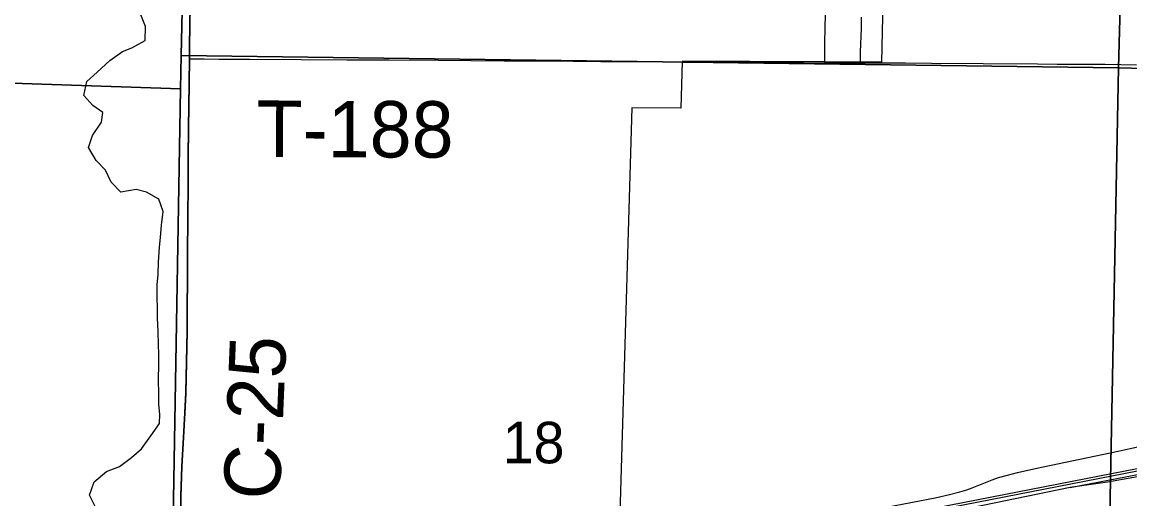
# Model space of a CAD drawing. Extents: x 0 to 34, y 0 to 22.
# Drawn here: x 5.615 to 6.731, y 18.139 to 18.619 of the extents above; entities that cross this region are included whole.
import ezdxf

# ---------------------------------------------------------------- set-up
doc = ezdxf.new("R2010")
doc.units = 0
for name, color, linetype in [('GM_X_City_Street', 7, 'Continuous'), ('GM_X_Corporation', 7, 'Continuous'), ('GM_X_County_Road', 7, 'Continuous'), ('GM_X_County_Road_Text', 7, 'Continuous'), ('GM_X_Minor_River', 7, 'Continuous'), ('GM_X_Rail_Line', 7, 'Continuous'), ('GM_X_Section_Text', 7, 'Continuous'), ('GM_X_Township_Road', 7, 'Continuous'), ('GM_X_Township_Road_Text', 7, 'Continuous')]:
    doc.layers.add(name, color=color, linetype=linetype)

msp = doc.modelspace()

# ---------------------------------------------------------------- linework, layer by layer
at = {"layer": 'GM_X_City_Street'}
msp.add_lwpolyline([(6.7198, 18.1874), (6.7348, 18.1907), (6.7634, 18.1967), (6.7983, 18.2033), (6.8423, 18.2119), (6.8863, 18.2201), (6.9106, 18.2247), (6.9292, 18.2281), (6.9377, 18.2295)], dxfattribs=at)
at = {"layer": 'GM_X_Corporation'}
for points in [[(6.7472, 19.5762), (6.72, 18.5734), (5.7756, 18.586), (5.7974, 19.5584), (5.7981, 19.5979)], [(4.8036, 19.5906), (5.7974, 19.5584), (5.7756, 18.586), (5.7749, 18.5522), (4.7775, 18.5857)], [(6.7486, 19.5865), (7.7504, 19.5655), (7.7346, 18.5471), (6.72, 18.5734), (6.7472, 19.5762)], [(4.7775, 18.5857), (5.7749, 18.5522), (5.7585, 17.5867), (5.7581, 17.5537), (4.7439, 17.5807)], [(5.7756, 18.586), (6.72, 18.5734), (6.7004, 17.5689), (5.7585, 17.5867), (5.7749, 18.5522)], [(6.72, 18.5734), (7.7346, 18.5471), (7.7016, 17.5373), (6.7004, 17.5689)]]:
    msp.add_lwpolyline(points, close=True, dxfattribs=at)
for points in [[(6.4924, 19.0846), (6.4812, 18.579), (6.4596, 18.5792), (6.4241, 18.5793), (6.3486, 18.5797), (6.2805, 18.5799), (6.2791, 18.5328), (6.2298, 18.5331), (6.2163, 18.0789)], [(5.7754, 18.121), (5.7754, 18.1421), (5.7765, 18.1719), (5.7779, 18.2011), (5.7795, 18.2259), (5.7805, 18.2463), (5.7818, 18.3085), (5.7822, 18.3843), (5.7823, 18.4241), (5.7826, 18.4557), (5.7829, 18.4831), (5.7832, 18.5129), (5.7839, 18.5576), (5.7841, 18.5832), (5.7841, 18.5931), (5.7845, 18.6185), (5.7851, 18.6508)], [(5.7851, 18.6508), (5.7845, 18.6185), (5.7841, 18.5931), (5.7841, 18.5832), (5.7839, 18.5576), (5.7832, 18.5129), (5.7829, 18.4831), (5.7826, 18.4557), (5.7823, 18.4241), (5.7822, 18.3843), (5.7818, 18.3085), (5.7805, 18.2463), (5.7795, 18.2259), (5.7779, 18.2011), (5.7765, 18.1719), (5.7754, 18.1421), (5.7754, 18.121)]]:
    msp.add_lwpolyline(points, dxfattribs=at)
at = {"layer": 'GM_X_County_Road'}
for points in [[(5.7843, 18.5826), (5.7844, 18.5925), (5.7847, 18.618), (5.7853, 18.6503), (5.7861, 18.6776), (5.7865, 18.6981), (5.787, 18.7354), (5.7874, 18.7485)], [(5.7774, 18.1855), (5.7781, 18.2005), (5.7797, 18.2253), (5.7807, 18.2458), (5.782, 18.3079), (5.7824, 18.3837), (5.7825, 18.4235), (5.7828, 18.4552), (5.7831, 18.4825), (5.7834, 18.5123), (5.7841, 18.5571), (5.7843, 18.5826)], [(5.7764, 18.0824), (5.7756, 18.1204), (5.7757, 18.1416), (5.7767, 18.1714), (5.7774, 18.1855)], [(6.2164, 18.0781), (6.2364, 18.0818), (6.2731, 18.0887), (6.3042, 18.0949), (6.348, 18.1038), (6.3925, 18.1126), (6.4413, 18.122), (6.4864, 18.131), (6.5352, 18.1404), (6.5498, 18.1436), (6.5601, 18.1462), (6.5673, 18.1484), (6.5726, 18.1502), (6.5842, 18.1549), (6.5928, 18.1583), (6.5992, 18.1606), (6.6081, 18.1632), (6.6183, 18.1658), (6.6377, 18.17), (6.6809, 18.1792), (6.7198, 18.1874)]]:
    msp.add_lwpolyline(points, dxfattribs=at)
at = {"layer": 'GM_X_Minor_River'}
msp.add_lwpolyline([(5.6906, 18.1282), (5.6832, 18.1428), (5.6881, 18.1563), (5.7004, 18.1667), (5.7134, 18.1718), (5.7257, 18.181), (5.7357, 18.1896), (5.7451, 18.2027), (5.754, 18.215), (5.7542, 18.2245), (5.7533, 18.2344), (5.7531, 18.2439), (5.753, 18.2602), (5.7533, 18.2738), (5.7531, 18.2845), (5.7529, 18.2947), (5.7524, 18.3073), (5.7519, 18.3217), (5.7517, 18.3316), (5.7516, 18.3418), (5.7514, 18.3547), (5.7524, 18.3653), (5.753, 18.3775), (5.7537, 18.3926), (5.755, 18.4025), (5.756, 18.415), (5.7574, 18.4286), (5.7531, 18.4412), (5.7407, 18.4483), (5.7305, 18.4508), (5.7149, 18.448), (5.7053, 18.4581), (5.6994, 18.4704), (5.6901, 18.48), (5.6824, 18.4931), (5.6864, 18.5051), (5.6954, 18.5186), (5.6968, 18.5285), (5.6867, 18.5355), (5.6777, 18.5455), (5.6807, 18.5595), (5.6911, 18.5692), (5.7038, 18.5807), (5.7165, 18.59), (5.7261, 18.5936), (5.7395, 18.6009), (5.7398, 18.6149), (5.7336, 18.6302)], dxfattribs=at)
at = {"layer": 'GM_X_Rail_Line'}
msp.add_line((6.6714, 18.1505), (8.0077, 18.4121), dxfattribs=at)
for points in [[(2.1, 17.2578), (2.1839, 17.2743), (2.7373, 17.3807), (3.3215, 17.4979), (3.9612, 17.6228), (4.5554, 17.74), (5.1565, 17.8564), (5.7754, 17.979), (6.3342, 18.0908), (6.9022, 18.2018), (7.3492, 18.2882), (7.4239, 18.3027), (8.0092, 18.4168), (8.4623, 18.5082), (8.9, 18.5958)], [(2.1, 17.2555), (2.1844, 17.272), (2.7377, 17.3784), (3.3219, 17.4956), (3.9616, 17.6205), (4.5558, 17.7377), (5.157, 17.8541), (5.7759, 17.9767), (6.3346, 18.0885), (6.9026, 18.1995), (7.3496, 18.2859), (7.4243, 18.3004), (8.0097, 18.4146), (8.4624, 18.5056), (8.9, 18.5934)], [(6.7516, 18.164), (6.7353, 18.1608), (6.709, 18.1559), (6.6714, 18.1505)], [(6.6714, 18.1505), (6.5393, 18.1236), (6.3844, 18.0928), (6.2895, 18.0748), (6.2521, 18.072)]]:
    msp.add_lwpolyline(points, dxfattribs=at)
at = {"layer": 'GM_X_Township_Road'}
for points in [[(6.4242, 18.5786), (6.4242, 18.5993), (6.4248, 18.6272)], [(6.4608, 18.6243), (6.4607, 18.613), (6.4599, 18.5895), (6.4599, 18.5857), (6.4597, 18.5785)], [(5.7843, 18.5826), (5.7886, 18.5826), (5.799, 18.5825), (5.814, 18.5822), (5.8307, 18.5822), (5.845, 18.5822), (5.8966, 18.5819), (5.9425, 18.5816), (5.9649, 18.5815), (5.9854, 18.5814), (6.0345, 18.581), (6.101, 18.5805), (6.1234, 18.5804), (6.1707, 18.58), (6.1986, 18.5797), (6.2353, 18.5797), (6.2689, 18.5794), (6.2806, 18.5792)], [(6.2806, 18.5792), (6.3183, 18.5792), (6.3487, 18.579), (6.3866, 18.5788), (6.4027, 18.5788), (6.4242, 18.5786)], [(6.4242, 18.5786), (6.4382, 18.5784), (6.4597, 18.5785), (6.4617, 18.5785), (6.4813, 18.5783)], [(6.4813, 18.5783), (6.5054, 18.5783), (6.5315, 18.5781), (6.5837, 18.5777), (6.6384, 18.5775), (6.6582, 18.5772), (6.7067, 18.577), (6.738, 18.5764)]]:
    msp.add_lwpolyline(points, dxfattribs=at)

# ---------------------------------------------------------------- texts
at = {"layer": 'GM_X_County_Road_Text'}
msp.add_text('C-25', height=0.05682, rotation=87.6286, dxfattribs=at).set_placement((5.8749, 18.1376))
at = {"layer": 'GM_X_Section_Text'}
msp.add_text('18', height=0.04186, rotation=0, dxfattribs=at).set_placement((6.0996, 18.175))
at = {"layer": 'GM_X_Township_Road_Text'}
msp.add_text('T-188', height=0.05682, rotation=359.7191, dxfattribs=at).set_placement((5.8515, 18.4838))

doc.saveas('drawing.dxf')
